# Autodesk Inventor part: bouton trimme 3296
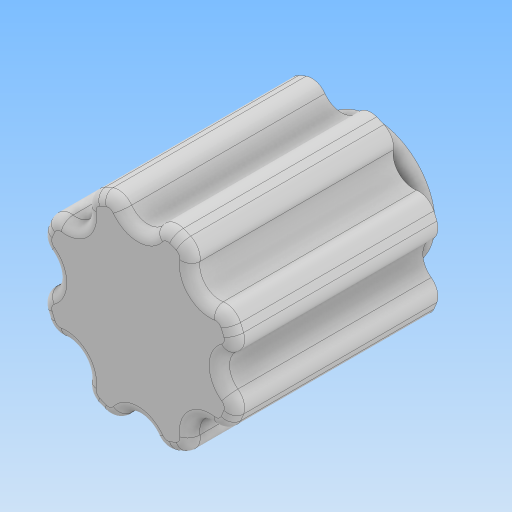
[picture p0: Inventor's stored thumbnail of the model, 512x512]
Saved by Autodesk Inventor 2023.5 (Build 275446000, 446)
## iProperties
Created: 2025-07
Part Number: bouton trimme 3296
Material: Générique
Document SubType Name: Modeling
Designer: admin
Density: 1 g/cm^3
Appearance: Par défaut
Author: admin
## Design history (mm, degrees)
sketch "Esquisse1"
  geometry: C1 r 1.1 at (0, 0); C2 r 3 at (0, 0); 1 further point
  constraints: 2 centre point, 2 coincident
  dimensions: "d0" = 2.2 diameter of C1; "d1" = 6 diameter of C2
extrude "Extrusion1" new body sketch "Esquisse1" distance "d2" = 1.6; taper "d3" = 0 deg
sketch "Esquisse2"
  geometry: L1 (-2.124, 0.25)-(2.334, 0.25); L2 (2.334, 0.25)-(2.334, -0.25); L3 (2.334, -0.25)-(-2.124, -0.25); L4 (-2.124, -0.25)-(-2.124, 0.25); 2 further points
  constraints: 8 end point, 2 parallel, 1 horizontal, 1 midpoint, 1 perpendicular
  dimensions: "d4" = 0.5 distance between parallel lines of L3 L1; "d5" = 0.25 vertical distance of point (0.105, 0.25) point (0, 0) (= 0.5 x d4)
extrude "Extrusion2" join sketch "Esquisse2" distance "d6" = 1.6; taper "d7" = 0 deg
sketch "Esquisse3"
  geometry: C1 r 5 at (0, 0); 1 further point
  constraints: 1 centre point, 1 coincident
  dimensions: "d8" = 10 diameter of C1
extrude "Extrusion3" join sketch "Esquisse3" distance "d9" = 10; taper "d10" = 0 deg
sketch "Esquisse4"
  geometry: L1 (0, 0)-(3.536, 3.536); L2 (0, 0)-(17.035, 0); L3 (0, 0)-(-3.536, -3.536); L4 (0, 0)-(-3.536, 3.536); L5 (0, 0)-(3.536, -3.536); C1 r 1 at (0, 5); C2 r 1 at (-5, 0); C3 r 1 at (5, 0); C4 r 1 at (0, -5); C5 r 1 at (-3.536, 3.536); C6 r 1 at (3.536, 3.536); C7 r 1 at (3.536, -3.536); C8 r 1 at (-3.536, -3.536); 14 further points
  constraints: 10 end point, 8 centre point, 4 coincident, 1 horizontal, 1 perpendicular, 1 point on line, 10 other
  dimensions: "d11" = 2 diameter of C1; "d12" = 2 diameter of C2; "d13" = 2 diameter of C3; "d14" = 2 diameter of C4; "d15" = 45 deg angle of L2 L1; "d16" = 2 diameter of C5; "d17" = 2 diameter of C6; "d18" = 2 diameter of C7; "d19" = 2 diameter of C8
extrude "Extrusion4" cut sketch "Esquisse4" distance "d20" = 10; taper "d21" = 0 deg
fillet "Congé1" dims "d22" = 0.8
fillet "Congé2" dims "d23" = 0.5
node "Solide1"
node "Boucle projetée1"
